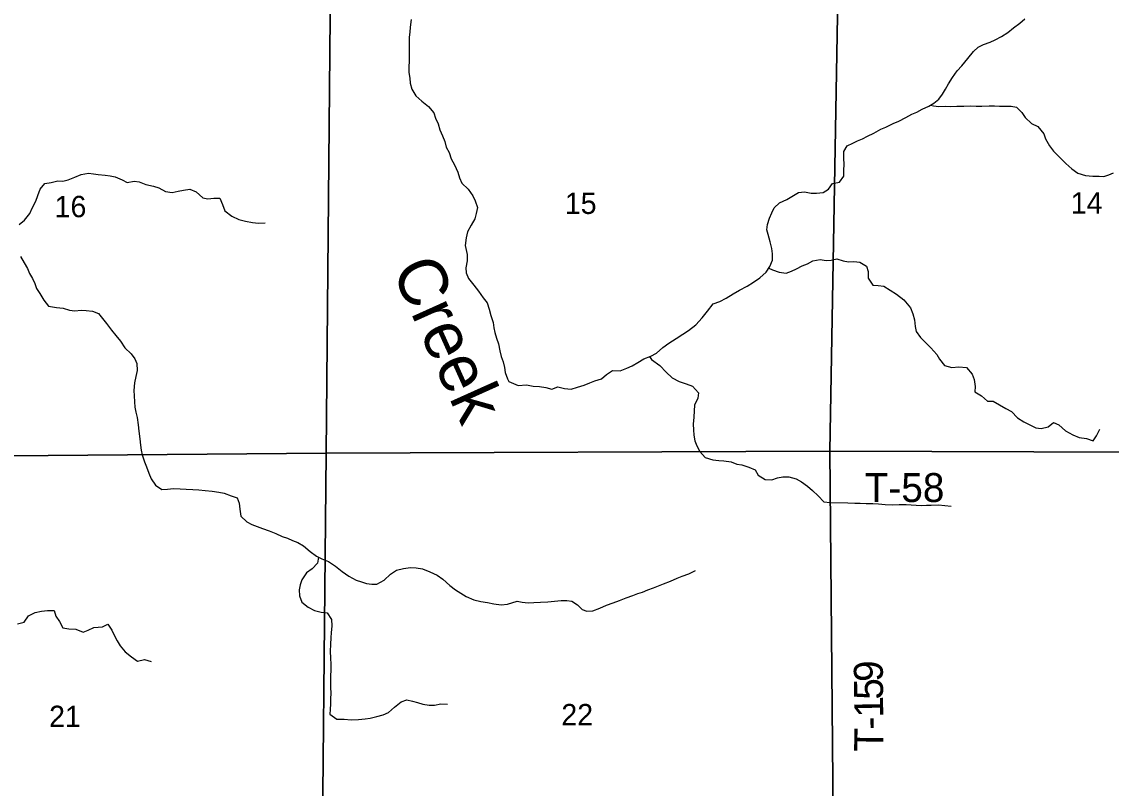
# Model space of a CAD drawing. Extents: x 1772825 to 1773716, y 1138558 to 1139032.
# Drawn here: x 1772829.187 to 1772830.255, y 1138559.298 to 1138560.049 of the extents above; entities that cross this region are included whole.
import ezdxf

# ---------------------------------------------------------------- set-up
doc = ezdxf.new("R2010")
doc.units = 0
for name, color, linetype in [('GM_X_Minor_River', 7, 'Continuous'), ('GM_X_Minor_River_Text', 7, 'Continuous'), ('GM_X_Section', 7, 'Continuous'), ('GM_X_Section_Text', 7, 'Continuous'), ('GM_X_Township_Road_Text', 7, 'Continuous')]:
    doc.layers.add(name, color=color, linetype=linetype)

msp = doc.modelspace()

# ---------------------------------------------------------------- linework, layer by layer
at = {"layer": 'GM_X_Minor_River'}
for points in [[(1772829.5688, 1138560.0512), (1772829.568, 1138560.0438), (1772829.5674, 1138560.039), (1772829.5668, 1138560.0339), (1772829.5669, 1138560.028), (1772829.5668, 1138560.0113), (1772829.5664, 1138560.0043), (1772829.5665, 1138559.9994), (1772829.5676, 1138559.9937), (1772829.568, 1138559.9889), (1772829.5694, 1138559.983), (1772829.5734, 1138559.9766)], [(1772829.6646, 1138559.6965), (1772829.6738, 1138559.6925), (1772829.6818, 1138559.6932), (1772829.6884, 1138559.692), (1772829.6945, 1138559.6914), (1772829.7007, 1138559.6904), (1772829.7066, 1138559.6889), (1772829.7125, 1138559.6911), (1772829.719, 1138559.6894), (1772829.7258, 1138559.689), (1772829.7317, 1138559.6907), (1772829.7383, 1138559.6927), (1772829.744, 1138559.6952), (1772829.7488, 1138559.6972), (1772829.7554, 1138559.6989), (1772829.7604, 1138559.7033), (1772829.7661, 1138559.7072), (1772829.7737, 1138559.7068), (1772829.7802, 1138559.7094), (1772829.7855, 1138559.7119), (1772829.791, 1138559.7149), (1772829.7967, 1138559.7187), (1772829.8036, 1138559.7213), (1772829.8094, 1138559.7243), (1772829.8155, 1138559.7296), (1772829.8214, 1138559.7339), (1772829.8285, 1138559.7387), (1772829.835, 1138559.7428), (1772829.8405, 1138559.7464), (1772829.8479, 1138559.752), (1772829.854, 1138559.759), (1772829.8592, 1138559.7655), (1772829.8647, 1138559.7725), (1772829.8713, 1138559.7747), (1772829.8776, 1138559.7781), (1772829.8843, 1138559.7823), (1772829.8907, 1138559.786), (1772829.898, 1138559.79), (1772829.9043, 1138559.7937), (1772829.9105, 1138559.7979), (1772829.9166, 1138559.8036), (1772829.9205, 1138559.8092), (1772829.9228, 1138559.8153), (1772829.923, 1138559.8216), (1772829.9222, 1138559.8269), (1772829.9207, 1138559.8333), (1772829.9187, 1138559.8404), (1772829.9174, 1138559.8451), (1772829.9182, 1138559.8504), (1772829.9199, 1138559.8567), (1772829.9222, 1138559.8618), (1772829.9247, 1138559.8667), (1772829.9298, 1138559.8716), (1772829.9369, 1138559.875), (1772829.942, 1138559.8777), (1772829.9483, 1138559.8818), (1772829.9544, 1138559.8823), (1772829.961, 1138559.8812), (1772829.9661, 1138559.881), (1772829.9726, 1138559.8817), (1772829.9777, 1138559.8851), (1772829.9819, 1138559.8904), (1772829.9886, 1138559.8919), (1772829.9928, 1138559.8977), (1772829.993, 1138559.9038), (1772829.9932, 1138559.9089), (1772829.993, 1138559.9158), (1772829.9929, 1138559.922), (1772829.9961, 1138559.9275), (1772830.0016, 1138559.93), (1772830.0064, 1138559.9324), (1772830.0111, 1138559.9343), (1772830.0161, 1138559.9369), (1772830.0222, 1138559.9399), (1772830.029, 1138559.9437), (1772830.034, 1138559.9458), (1772830.0412, 1138559.9495), (1772830.0467, 1138559.9518), (1772830.0537, 1138559.9554), (1772830.0594, 1138559.9584), (1772830.0644, 1138559.9606), (1772830.0695, 1138559.9634), (1772830.076, 1138559.9665), (1772830.0811, 1138559.9693), (1772830.0861, 1138559.9732), (1772830.0895, 1138559.9782), (1772830.0924, 1138559.9831), (1772830.0953, 1138559.9884), (1772830.0993, 1138559.9944), (1772830.1038, 1138560.0011), (1772830.1086, 1138560.006), (1772830.1145, 1138560.0132), (1772830.1199, 1138560.02), (1772830.1246, 1138560.0243), (1772830.1298, 1138560.0269), (1772830.1362, 1138560.029), (1772830.1412, 1138560.0315), (1772830.1473, 1138560.0348), (1772830.1537, 1138560.0386), (1772830.1591, 1138560.0433), (1772830.1652, 1138560.0479)], [(1772830.1652, 1138560.0479), (1772830.1703, 1138560.052)], [(1772829.5734, 1138559.9766), (1772829.5794, 1138559.9714), (1772829.5858, 1138559.9662), (1772829.5909, 1138559.9597), (1772829.5927, 1138559.9546), (1772829.5954, 1138559.9489), (1772829.5968, 1138559.9432), (1772829.5994, 1138559.9373), (1772829.6017, 1138559.9318), (1772829.603, 1138559.9261), (1772829.606, 1138559.9211), (1772829.6082, 1138559.9148), (1772829.6112, 1138559.9089), (1772829.6146, 1138559.9017), (1772829.6162, 1138559.896), (1772829.6185, 1138559.8908), (1772829.6247, 1138559.8849), (1772829.6294, 1138559.8786), (1772829.6314, 1138559.8735), (1772829.6337, 1138559.867), (1772829.6327, 1138559.861), (1772829.6311, 1138559.8558), (1772829.6278, 1138559.8496), (1772829.6242, 1138559.8432), (1772829.6228, 1138559.8373), (1772829.6218, 1138559.8297), (1772829.6238, 1138559.821), (1772829.6238, 1138559.8147), (1772829.6224, 1138559.8079), (1772829.6229, 1138559.803), (1772829.625, 1138559.7975), (1772829.6301, 1138559.7908), (1772829.6348, 1138559.7849), (1772829.6395, 1138559.7784), (1772829.6432, 1138559.7736), (1772829.6454, 1138559.7675), (1772829.6469, 1138559.7612), (1772829.6493, 1138559.7542), (1772829.6499, 1138559.7491), (1772829.6508, 1138559.7443), (1772829.6524, 1138559.7388), (1772829.6545, 1138559.7333), (1772829.6558, 1138559.7266), (1772829.6569, 1138559.7209), (1772829.6591, 1138559.7156), (1772829.6602, 1138559.7101), (1772829.6611, 1138559.7054), (1772829.6632, 1138559.6991), (1772829.6646, 1138559.6965)], [(1772830.0777, 1138559.9674), (1772830.0807, 1138559.9668), (1772830.0859, 1138559.9662), (1772830.0925, 1138559.9664), (1772830.0972, 1138559.9662), (1772830.1035, 1138559.9663), (1772830.1105, 1138559.9663), (1772830.1174, 1138559.9667), (1772830.1227, 1138559.9663), (1772830.1282, 1138559.9664), (1772830.1354, 1138559.9668), (1772830.1405, 1138559.9668), (1772830.1455, 1138559.9665), (1772830.1521, 1138559.9663), (1772830.157, 1138559.9663), (1772830.1622, 1138559.9653), (1772830.1674, 1138559.9602), (1772830.1706, 1138559.9552), (1772830.1769, 1138559.9493), (1772830.1831, 1138559.9463), (1772830.1888, 1138559.9392), (1772830.1905, 1138559.9345), (1772830.1943, 1138559.9274), (1772830.1984, 1138559.9223), (1772830.205, 1138559.9158), (1772830.2103, 1138559.9103), (1772830.2162, 1138559.9048), (1772830.2222, 1138559.9008), (1772830.2298, 1138559.8983), (1772830.2368, 1138559.8978), (1772830.2431, 1138559.8976), (1772830.2478, 1138559.8974), (1772830.2526, 1138559.8989), (1772830.2573, 1138559.901)], [(1772829.1846, 1138559.8505), (1772829.19, 1138559.8546), (1772829.195, 1138559.861), (1772829.1975, 1138559.8663), (1772829.2011, 1138559.8733), (1772829.2031, 1138559.8788), (1772829.2052, 1138559.885), (1772829.2098, 1138559.8907), (1772829.2159, 1138559.8916), (1772829.2227, 1138559.8933), (1772829.2276, 1138559.8928), (1772829.2328, 1138559.8941), (1772829.2392, 1138559.8969), (1772829.2455, 1138559.8995), (1772829.2525, 1138559.9006), (1772829.2575, 1138559.9), (1772829.2622, 1138559.8994), (1772829.2688, 1138559.8986), (1772829.2738, 1138559.8982), (1772829.2789, 1138559.8972), (1772829.2855, 1138559.8943), (1772829.2904, 1138559.8916), (1772829.2973, 1138559.8929), (1772829.3024, 1138559.8921), (1772829.3088, 1138559.8896), (1772829.3162, 1138559.8878), (1772829.3215, 1138559.8864), (1772829.3281, 1138559.8826), (1772829.3346, 1138559.8816), (1772829.3406, 1138559.8829), (1772829.3456, 1138559.884), (1772829.3518, 1138559.8849), (1772829.3583, 1138559.8824), (1772829.3647, 1138559.8766), (1772829.3696, 1138559.8756), (1772829.3753, 1138559.8762), (1772829.3814, 1138559.8763), (1772829.384, 1138559.87), (1772829.3862, 1138559.8636), (1772829.3932, 1138559.8586), (1772829.4, 1138559.8553), (1772829.4066, 1138559.8536), (1772829.4133, 1138559.8524), (1772829.4193, 1138559.8517), (1772829.4258, 1138559.8521)], [(1772829.1861, 1138559.819), (1772829.1897, 1138559.8129)], [(1772829.1897, 1138559.8129), (1772829.1927, 1138559.8073), (1772829.1949, 1138559.8024), (1772829.1979, 1138559.7973), (1772829.2001, 1138559.7925), (1772829.2018, 1138559.7877), (1772829.205, 1138559.7828), (1772829.2089, 1138559.7763), (1772829.2135, 1138559.7702), (1772829.2212, 1138559.769), (1772829.2279, 1138559.7684), (1772829.2341, 1138559.7664), (1772829.2392, 1138559.7658), (1772829.2455, 1138559.7662), (1772829.2502, 1138559.7659), (1772829.2567, 1138559.7653), (1772829.2625, 1138559.763), (1772829.2665, 1138559.7582), (1772829.2701, 1138559.7533), (1772829.2753, 1138559.7466), (1772829.2795, 1138559.7416), (1772829.284, 1138559.7361), (1772829.2883, 1138559.7294), (1772829.2943, 1138559.7235), (1772829.2981, 1138559.7187), (1772829.2999, 1138559.714), (1772829.3003, 1138559.7071), (1772829.2991, 1138559.7013), (1772829.2977, 1138559.695), (1772829.2969, 1138559.6876), (1772829.2974, 1138559.6825), (1772829.2978, 1138559.6766), (1772829.2981, 1138559.6713), (1772829.299, 1138559.6662), (1772829.3003, 1138559.661), (1772829.3012, 1138559.6538), (1772829.3019, 1138559.6477), (1772829.3028, 1138559.6403), (1772829.3037, 1138559.6341), (1772829.3041, 1138559.6291), (1772829.3052, 1138559.6244), (1772829.3076, 1138559.6175), (1772829.3093, 1138559.6128), (1772829.3119, 1138559.6067), (1772829.3141, 1138559.601), (1772829.3182, 1138559.5949), (1772829.3245, 1138559.5904), (1772829.3302, 1138559.5908), (1772829.336, 1138559.5915), (1772829.3425, 1138559.5913), (1772829.3484, 1138559.5908), (1772829.3548, 1138559.5906), (1772829.3609, 1138559.5902), (1772829.3668, 1138559.5897), (1772829.3738, 1138559.5889), (1772829.3802, 1138559.5879), (1772829.3855, 1138559.5868), (1772829.3925, 1138559.5842), (1772829.3982, 1138559.5823), (1772829.4004, 1138559.5772), (1772829.4008, 1138559.5711), (1772829.4019, 1138559.5644), (1772829.4077, 1138559.5589), (1772829.4128, 1138559.5562), (1772829.4179, 1138559.5541), (1772829.4232, 1138559.5523), (1772829.4297, 1138559.55), (1772829.4363, 1138559.5473), (1772829.4425, 1138559.5444), (1772829.4478, 1138559.5427), (1772829.4527, 1138559.5405), (1772829.4578, 1138559.5386), (1772829.4633, 1138559.5353), (1772829.4697, 1138559.5298), (1772829.4761, 1138559.525), (1772829.4813, 1138559.5227), (1772829.4879, 1138559.5198), (1772829.4947, 1138559.5152), (1772829.5011, 1138559.5102), (1772829.5079, 1138559.5054), (1772829.5149, 1138559.5017), (1772829.5202, 1138559.5), (1772829.5251, 1138559.4984), (1772829.5302, 1138559.4976), (1772829.5351, 1138559.4978), (1772829.5424, 1138559.5015), (1772829.5487, 1138559.5074), (1772829.5544, 1138559.5113), (1772829.5614, 1138559.513), (1772829.5683, 1138559.5139), (1772829.5738, 1138559.5138), (1772829.58, 1138559.5126), (1772829.587, 1138559.5099), (1772829.5942, 1138559.5065), (1772829.5999, 1138559.5026), (1772829.6067, 1138559.4965), (1772829.6123, 1138559.4921), (1772829.6174, 1138559.4888), (1772829.6229, 1138559.4856), (1772829.6303, 1138559.4825), (1772829.6371, 1138559.4807)], [(1772829.9194, 1138559.8077), (1772829.9231, 1138559.8058), (1772829.9294, 1138559.8037), (1772829.9364, 1138559.8027), (1772829.9415, 1138559.8046), (1772829.9466, 1138559.8069), (1772829.952, 1138559.8097), (1772829.9573, 1138559.8119), (1772829.9626, 1138559.8148), (1772829.9698, 1138559.8159), (1772829.9755, 1138559.8149), (1772829.9806, 1138559.8154), (1772829.986, 1138559.8167), (1772829.9922, 1138559.8146), (1772829.9973, 1138559.8138), (1772830.0025, 1138559.8142), (1772830.0087, 1138559.8134), (1772830.015, 1138559.8096), (1772830.0167, 1138559.8043), (1772830.0166, 1138559.7976), (1772830.0212, 1138559.791), (1772830.0265, 1138559.7904), (1772830.0322, 1138559.7898), (1772830.0382, 1138559.786), (1772830.0445, 1138559.7821), (1772830.0516, 1138559.7764), (1772830.0583, 1138559.7688), (1772830.0605, 1138559.7627), (1772830.062, 1138559.7568), (1772830.0629, 1138559.7504), (1772830.0637, 1138559.7454), (1772830.068, 1138559.7395), (1772830.0782, 1138559.7293), (1772830.0839, 1138559.723), (1772830.0867, 1138559.7182), (1772830.0916, 1138559.7121), (1772830.0988, 1138559.71), (1772830.1055, 1138559.7107), (1772830.1132, 1138559.7103), (1772830.1187, 1138559.7037), (1772830.1206, 1138559.6983), (1772830.1217, 1138559.6915), (1772830.1213, 1138559.6864), (1772830.1279, 1138559.6825), (1772830.1338, 1138559.6772), (1772830.1393, 1138559.6772), (1772830.1454, 1138559.6734), (1772830.1516, 1138559.6701), (1772830.1573, 1138559.6671), (1772830.1631, 1138559.6608), (1772830.1692, 1138559.6569), (1772830.1751, 1138559.6539), (1772830.1811, 1138559.651), (1772830.1864, 1138559.6502), (1772830.1931, 1138559.6519), (1772830.1982, 1138559.6563), (1772830.2035, 1138559.654), (1772830.21, 1138559.6482), (1772830.2172, 1138559.644), (1772830.2236, 1138559.6415), (1772830.2306, 1138559.6404), (1772830.2373, 1138559.6381), (1772830.2405, 1138559.6432), (1772830.2436, 1138559.6496)], [(1772829.8025, 1138559.7209), (1772829.8045, 1138559.7181), (1772829.8126, 1138559.7122), (1772829.8189, 1138559.7057), (1772829.8247, 1138559.7001), (1772829.8315, 1138559.6963), (1772829.8382, 1138559.6942), (1772829.8444, 1138559.6917), (1772829.8503, 1138559.6854), (1772829.8497, 1138559.6801), (1772829.8466, 1138559.6731), (1772829.8462, 1138559.6678), (1772829.846, 1138559.6613), (1772829.8452, 1138559.6545), (1772829.8456, 1138559.649), (1772829.8459, 1138559.6439), (1772829.8469, 1138559.6382), (1772829.8487, 1138559.6334), (1772829.8519, 1138559.6277), (1772829.857, 1138559.6218), (1772829.8644, 1138559.6197), (1772829.8703, 1138559.6189), (1772829.8752, 1138559.6187), (1772829.8824, 1138559.6175), (1772829.8881, 1138559.6152), (1772829.8929, 1138559.6148), (1772829.8999, 1138559.6125), (1772829.9061, 1138559.6097), (1772829.909, 1138559.6045), (1772829.9158, 1138559.6003), (1772829.9222, 1138559.6001), (1772829.9277, 1138559.6018), (1772829.9331, 1138559.6031), (1772829.9388, 1138559.6029), (1772829.9463, 1138559.6011), (1772829.9514, 1138559.5981), (1772829.9571, 1138559.5939), (1772829.9622, 1138559.5897), (1772829.9677, 1138559.5844), (1772829.9732, 1138559.5783), (1772829.9796, 1138559.5777), (1772829.9967, 1138559.5776), (1772830.0036, 1138559.5772), (1772830.0089, 1138559.5772), (1772830.0146, 1138559.5769), (1772830.0212, 1138559.5767), (1772830.0269, 1138559.5765), (1772830.0335, 1138559.5757), (1772830.0402, 1138559.5755), (1772830.047, 1138559.5759), (1772830.0538, 1138559.5758), (1772830.059, 1138559.5754), (1772830.0637, 1138559.575), (1772830.069, 1138559.5748), (1772830.0738, 1138559.5752), (1772830.0785, 1138559.5753), (1772830.0855, 1138559.5755), (1772830.092, 1138559.5749), (1772830.0982, 1138559.5741)], [(1772829.4781, 1138559.5241), (1772829.477, 1138559.5183), (1772829.4719, 1138559.5129), (1772829.4662, 1138559.5087), (1772829.4616, 1138559.5021), (1772829.46, 1138559.4972), (1772829.4592, 1138559.4923), (1772829.4594, 1138559.4862), (1772829.4616, 1138559.4799), (1772829.468, 1138559.4753), (1772829.4741, 1138559.4719), (1772829.4807, 1138559.4701), (1772829.4864, 1138559.4697), (1772829.4909, 1138559.4632), (1772829.4912, 1138559.4568), (1772829.4906, 1138559.4501), (1772829.4902, 1138559.4454), (1772829.4897, 1138559.4384), (1772829.4895, 1138559.4321), (1772829.4898, 1138559.4251), (1772829.49, 1138559.4194), (1772829.4901, 1138559.4131), (1772829.4899, 1138559.408), (1772829.4897, 1138559.4031), (1772829.4898, 1138559.3968), (1772829.49, 1138559.3904), (1772829.4897, 1138559.3856), (1772829.4897, 1138559.3805), (1772829.4895, 1138559.3748), (1772829.4891, 1138559.3701), (1772829.496, 1138559.3653), (1772829.5031, 1138559.3652), (1772829.5101, 1138559.3648), (1772829.5173, 1138559.3651), (1772829.5237, 1138559.3656), (1772829.5285, 1138559.3664), (1772829.5353, 1138559.368), (1772829.5414, 1138559.3697), (1772829.5466, 1138559.3719), (1772829.5525, 1138559.3772), (1772829.559, 1138559.3823), (1772829.5647, 1138559.3843), (1772829.57, 1138559.3831), (1772829.5751, 1138559.3818), (1772829.5804, 1138559.3802), (1772829.5866, 1138559.379), (1772829.5916, 1138559.379), (1772829.598, 1138559.3803), (1772829.6043, 1138559.38)], [(1772829.6631, 1138559.478), (1772829.6727, 1138559.481), (1772829.6777, 1138559.4799), (1772829.6834, 1138559.4795), (1772829.6892, 1138559.4796), (1772829.6955, 1138559.48), (1772829.7029, 1138559.4805), (1772829.7092, 1138559.4811), (1772829.716, 1138559.4816), (1772829.7213, 1138559.4816), (1772829.7262, 1138559.481), (1772829.7317, 1138559.4776), (1772829.7363, 1138559.4728), (1772829.741, 1138559.4713), (1772829.7469, 1138559.4716), (1772829.7537, 1138559.4742), (1772829.7602, 1138559.4771), (1772829.7667, 1138559.4795), (1772829.7729, 1138559.4818), (1772829.7796, 1138559.4842), (1772829.7861, 1138559.4866), (1772829.791, 1138559.4885), (1772829.7957, 1138559.49), (1772829.8007, 1138559.4921), (1772829.8062, 1138559.4941), (1772829.8113, 1138559.4962), (1772829.8161, 1138559.4981), (1772829.8229, 1138559.5007), (1772829.8294, 1138559.5037), (1772829.8343, 1138559.5054), (1772829.8408, 1138559.5078), (1772829.8475, 1138559.5112)], [(1772829.6371, 1138559.4807), (1772829.6437, 1138559.4797), (1772829.65, 1138559.4783), (1772829.6572, 1138559.4775), (1772829.6631, 1138559.478)], [(1772829.1829, 1138559.4589), (1772829.1896, 1138559.4605), (1772829.1938, 1138559.4666), (1772829.2005, 1138559.4698), (1772829.2065, 1138559.4712), (1772829.2124, 1138559.4718), (1772829.2191, 1138559.4719), (1772829.2207, 1138559.4664), (1772829.2241, 1138559.461), (1772829.2275, 1138559.4549), (1772829.2335, 1138559.454), (1772829.2402, 1138559.4537), (1772829.2474, 1138559.4506), (1772829.2523, 1138559.4525), (1772829.258, 1138559.4551), (1772829.2662, 1138559.456), (1772829.2717, 1138559.4586), (1772829.2756, 1138559.4527), (1772829.2779, 1138559.4477), (1772829.2807, 1138559.4422), (1772829.2837, 1138559.4374), (1772829.2886, 1138559.4315), (1772829.2946, 1138559.4264), (1772829.3005, 1138559.4223), (1772829.3075, 1138559.4238), (1772829.3141, 1138559.4219)]]:
    msp.add_lwpolyline(points, dxfattribs=at)
at = {"layer": 'GM_X_Section'}
for points in [[(1772829.988, 1138560.1296), (1772829.979, 1138559.628), (1772829.4854, 1138559.6261), (1772829.4902, 1138560.1262)], [(1772829.988, 1138560.1296), (1772830.4798, 1138560.1277), (1772830.4786, 1138559.6266), (1772829.979, 1138559.628)], [(1772829.4902, 1138560.1262), (1772829.4854, 1138559.6261), (1772828.9792, 1138559.622), (1772828.9871, 1138560.1228)], [(1772829.4854, 1138559.6261), (1772829.979, 1138559.628), (1772829.9838, 1138559.1258), (1772829.4805, 1138559.1253)], [(1772829.979, 1138559.628), (1772830.4786, 1138559.6266), (1772830.471, 1138559.1272), (1772829.9838, 1138559.1258)], [(1772828.9792, 1138559.622), (1772829.4854, 1138559.6261), (1772829.4805, 1138559.1253), (1772828.9742, 1138559.1237)]]:
    msp.add_lwpolyline(points, close=True, dxfattribs=at)

# ---------------------------------------------------------------- texts
at = {"layer": 'GM_X_Minor_River_Text'}
msp.add_text('Creek', height=0.04737, rotation=294.2228, dxfattribs=at).set_placement((1772829.5493, 1138559.806))
at = {"layer": 'GM_X_Section_Text'}
for s, p in [('16', (1772829.2194, 1138559.8575)), ('15', (1772829.7194, 1138559.8607)), ('14', (1772830.2152, 1138559.861)), ('21', (1772829.214, 1138559.3576)), ('22', (1772829.716, 1138559.3593))]:
    msp.add_text(s, height=0.02093, rotation=0, dxfattribs=at).set_placement(p)
at = {"layer": 'GM_X_Township_Road_Text'}
for s, height, rotation, p in [('T-58', 0.02841, 0, (1772830.0133, 1138559.5782)), ('9', 0.0284, 90.6077, (1772830.0312, 1138559.402)), ('5', 0.0284, 90.5909, (1772830.0314, 1138559.3845)), ('1', 0.0284, 90.5268, (1772830.0315, 1138559.367)), ('-', 0.0284, 90.3381, (1772830.0316, 1138559.3552)), ('T', 0.0284, 89.28, (1772830.0313, 1138559.3334))]:
    msp.add_text(s, height=height, rotation=rotation, dxfattribs=at).set_placement(p)

doc.saveas('drawing.dxf')
